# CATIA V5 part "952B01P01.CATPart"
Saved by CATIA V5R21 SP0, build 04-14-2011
Part number: 952B01P01
Bounding box of the stored display mesh (mm): x -33.4 to 33.4, y -127 to 127, z -8 to 8
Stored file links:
  C:\Users\ALI OZGUN\Desktop\alhan\952B01P01.CATPart
  C:\Users\ALI OZGUN\Desktop\alhan\943B01P01.CATPart
  C:\Users\ALI OZGUN\Desktop\alhan\950B01P01.CATPart
  C:\Users\ALI OZGUN\Desktop\alhan\Product1.CATProduct
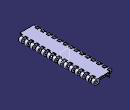
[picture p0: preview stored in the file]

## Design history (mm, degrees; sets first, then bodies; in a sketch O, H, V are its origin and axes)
Body1 (main body)
Body2
  Sketch1 on zx-plane, origin (0, 0, 0), H (-1, 0, 0), V (0, 0, 1)
    construction line L1 (25.4, 8) -> (25.4, -8)
    line L2 (25.4, -8) -> (-25.4, -8)
    construction line L3 (-25.4, -8) -> (-25.4, 8)
    line L4 (-25.4, 8) -> (25.4, 8)
    point P3 (-25.4, -8)
    arc A1 centre (25.4, 0) radius 8 from (25.4, 8) to (25.4, -8) cw
    arc A2 centre (-25.4, 0) radius 8 from (-25.4, 8) to (-25.4, -8) ccw
    point P7 (-25.4, -8)
    length L4 = 50.8
    length L3 = 16
    vertical: L1 V, L3 V
    horizontal: L2 H, L4 H
    equidistance: L1 L3 O, L2 L4 O
    tangency: A1 L2, A2 L4, A2 L2, L4 A1
    coincidence: P7 L2, P3 P7
  Pad1: profile Sketch1, direction (0, 1, 0), length 127, mirrored extent
  Sketch2 on zx-plane, origin (0, 0, 0), H (-1, 0, 0), V (0, 0, 1)
    circle A1 centre (25.4, 0) radius 3.15
    circle A2 centre (-25.4, 0) radius 3.15
  Pocket1: profile Sketch2, direction (0, -1, 0), length 204, mirrored extent
  Body3
    Solid1: solid without history
    Body4
      Solid2: solid without history
    Add1: tool Body4
  Remove1: tool Body3
  RemoveFace1: RemoveFaces (face of Solid1; face of Pocket1 from Sketch2.A2; face of Pad1 from Sketch1.A2; face of Solid2; face of Solid2)
  Body5
    Solid3: solid without history
  Remove2: tool Body5
  Body6
    Sketch3 on face of Pad1 from Sketch1.L4, origin (0, 0, 8), H (1, 0, 0), V (0, 1, 0)
      line L1 (-14.4, -112.8) -> (14.4, -112.8)
      line L2 (14.4, -112.8) -> (14.4, -124)
      line L3 (14.4, -124) -> (-14.4, -124)
      line L4 (-14.4, -124) -> (-14.4, -112.8)
    Pad2: profile Sketch3, direction (0, 0, -1), length 13, opposite side length 4
    Sketch4 on face of Pad2 from Sketch3.L3, origin (0, -124, 0), H (1, 0, 0), V (0, 0, 1)
      line L1 (17.4, 8) -> (14.4, 2)
      line L2 (-17.4, 8) -> (-14.4, 2)
      line L3 (19.4, 8) -> (19.4, 12)
      line L4 (-25.4, 8) -> (-25.4, 12)
      line L5 (14.4, -5) -> (-14.4, -5)
      construction line L6 (-25.4, 8) -> (19.4, 8)
      line L7 (17.4, 8) -> (19.4, 8)
      line L8 (-25.4, 8) -> (-17.4, 8)
      construction line L9 (14.4, 12) -> (14.4, -5)
      line L10 (14.4, 2) -> (14.4, -5)
      construction line L11 (-14.4, 12) -> (-14.4, -5)
      line L12 (-14.4, 2) -> (-14.4, -5)
      construction line L13 (-14.4, 12) -> (14.4, 12)
      line L14 (-25.4, 12) -> (19.4, 12)
    Pad3: profile Sketch4, direction (0, 1, 0), length 12
    RectPattern1: of the body so far, direction 1 instances 15, spacing 18.6, along yz-plane
    Symmetry1: Reference xy-plane, ToTransfor RectPattern1
    Body7
      Sketch5 on face of Pad1, origin (0, 0, -8), H (1, 0, 0), V (0, -1, 0)
        line L1 (-14.4, 111) -> (14.4, 111)
        line L2 (14.4, 111) -> (14.4, 106.4)
        line L3 (14.4, 106.4) -> (-14.4, 106.4)
        line L4 (-14.4, 106.4) -> (-14.4, 111)
      Pad4: profile Sketch5, direction (0, 0, 1), length 12, opposite side length 13
      RectPattern2: of the body so far, direction 1 instances 14, spacing 18.6, along edge [face of Pad1 | face of RectPattern1] reversed
    Add2: tool Body7
  Remove3: tool Body6
  Sketch6 on zx-plane, origin (0, 0, 0), H (-1, 0, 0), V (0, 0, 1)
    line L1 (0, 72) -> (0, 6.9718)
    point P1 (0, 72)
    reference projected line E1 (-25.4, -8) -> (25.4, -8) from edge [face of Pad1 from Sketch1.L2 | end face of Pad1]
    distance P1 E1 = 80
    coincidence: P1 V
    vertical: L1 V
